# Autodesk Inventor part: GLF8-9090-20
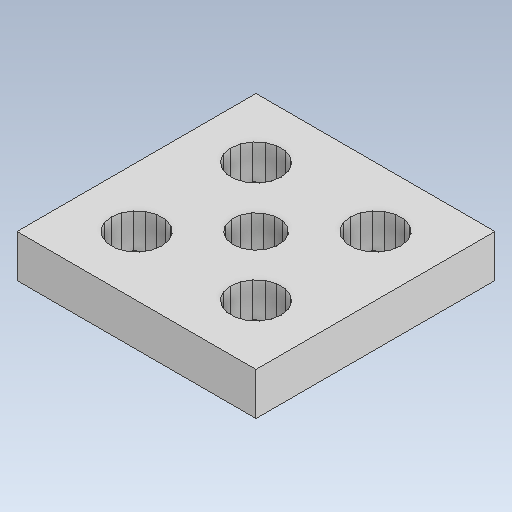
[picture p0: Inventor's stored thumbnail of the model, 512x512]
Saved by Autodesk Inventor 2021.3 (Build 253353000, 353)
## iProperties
Created: 2022-02
Part Number: GLF8-9090-20
Material: 一般
Document SubType Name: Modeling
Designer: kengo
Density: 1 g/cm^3
Appearance: 既定
Author: kengo
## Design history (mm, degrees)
feature "GLF8-9090-20"
node "ソリッド1"
